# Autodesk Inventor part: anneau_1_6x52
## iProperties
Created: 2011-01
Part Number: anneau_1_6x52
Document SubType Name: Modeling
Designer: eric
Density: 1 g/cm^3
Mass: 0.32846 g
Surface Area: 8.21151 cm^2
Volume: 0.32846 cm^3
Author: eric
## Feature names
1. Base1
